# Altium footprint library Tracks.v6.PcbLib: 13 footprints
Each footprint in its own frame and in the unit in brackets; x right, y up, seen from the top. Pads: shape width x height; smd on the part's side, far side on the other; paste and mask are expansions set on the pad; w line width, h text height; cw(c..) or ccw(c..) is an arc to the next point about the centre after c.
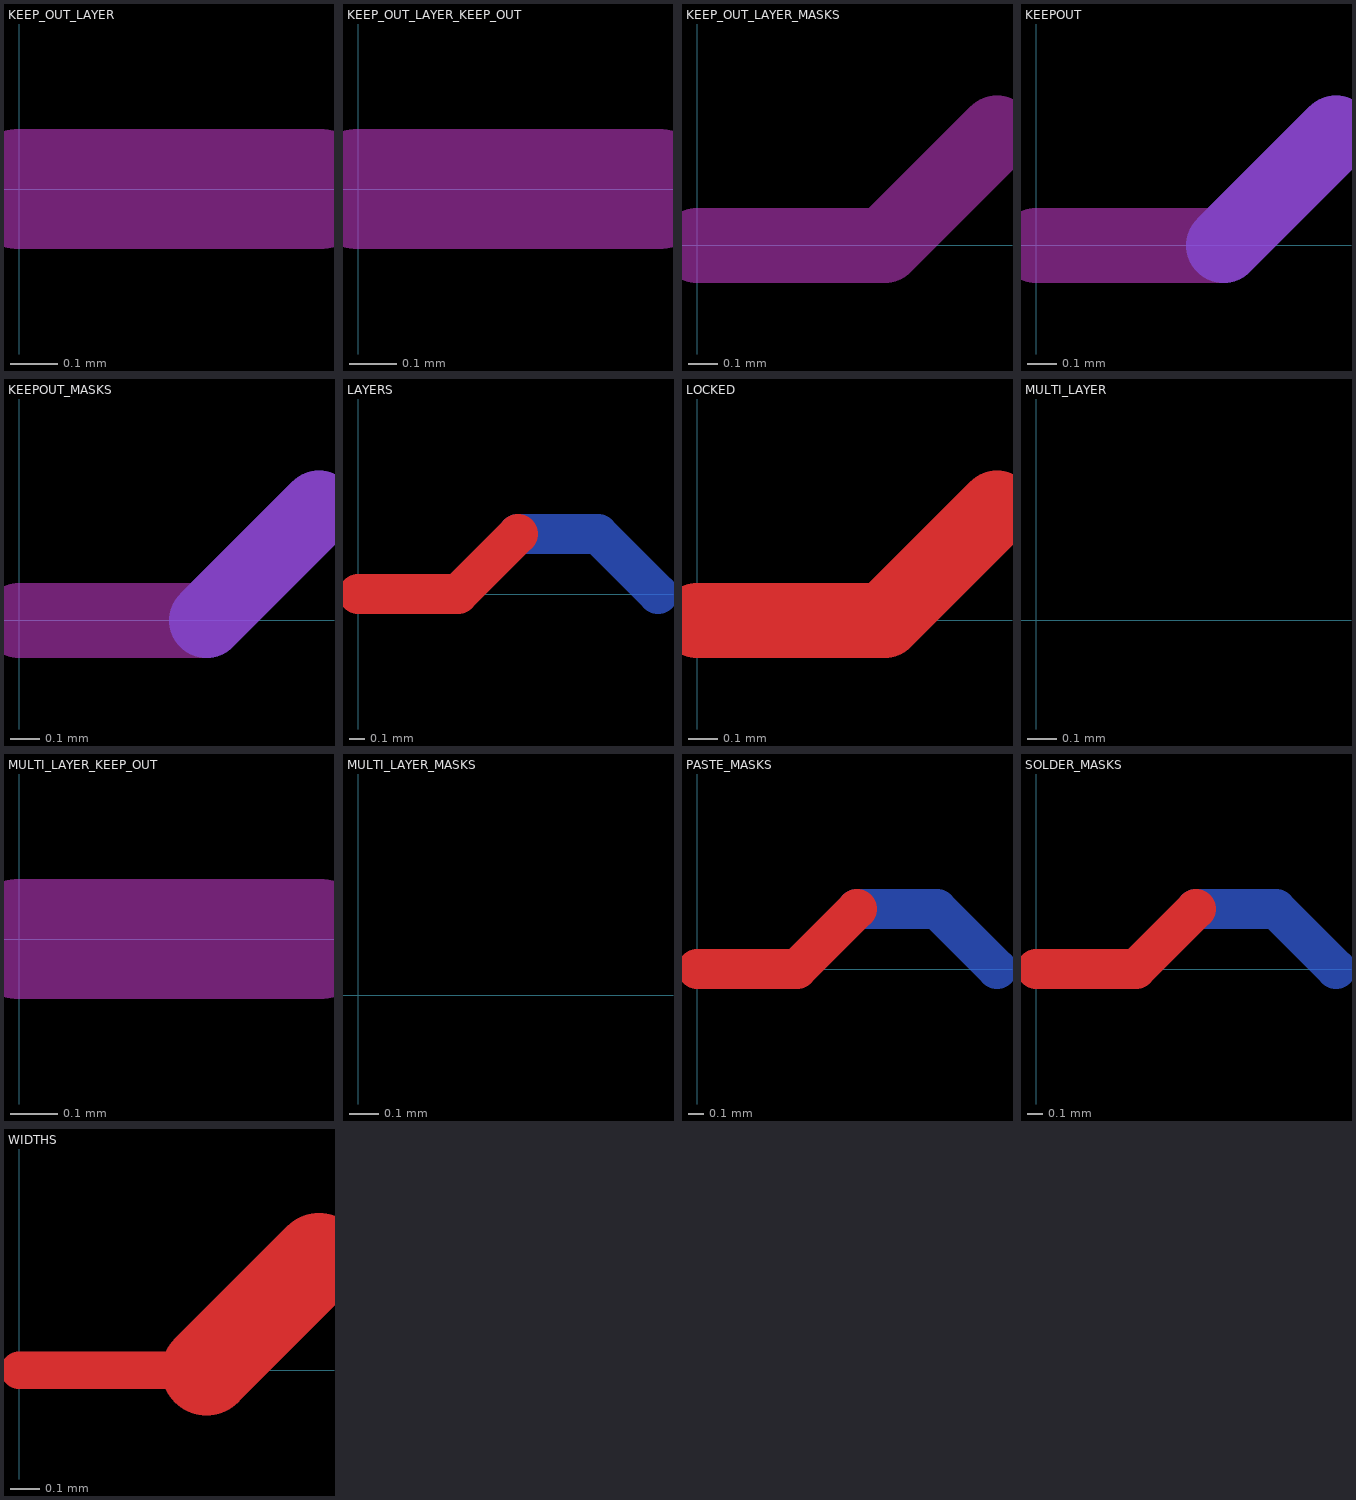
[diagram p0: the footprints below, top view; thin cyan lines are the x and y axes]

## KEEP_OUT_LAYER [mm]
Keep-Out Layer:
  lines w0.254: 0,0 0.635,0

## KEEP_OUT_LAYER_KEEP_OUT [mm]
Keep-Out Layer:
  lines w0.254: 0,0 0.635,0

## KEEP_OUT_LAYER_MASKS [mm]
Keep-Out Layer:
  lines w0.254: 0,0 0.635,0 1.016,0.381

## KEEPOUT [mm]
Top Layer keep-out:
  lines w0.254: 0,0 0.635,0
Bottom Layer keep-out:
  lines w0.254: 0.635,0 1.016,0.381

## KEEPOUT_MASKS [mm]
Top Layer keep-out:
  lines w0.254: 0,0 0.635,0
Bottom Layer keep-out:
  lines w0.254: 0.635,0 1.016,0.381

## LAYERS [mm]
Top Layer:
  lines w0.254: 0,0 0.635,0 1.016,0.381
Bottom Layer:
  lines w0.254: 1.016,0.381 1.524,0.381 1.905,0

## LOCKED [mm]
Top Layer:
  lines w0.254: 0,0 0.635,0 1.016,0.381

## MULTI_LAYER [mm]
Multi-Layer:
  lines w0.254: 0,0 0.635,0 1.016,0.381

## MULTI_LAYER_KEEP_OUT [mm]
Multi-Layer keep-out:
  lines w0.254: 0,0 0.635,0

## MULTI_LAYER_MASKS [mm]
Multi-Layer:
  lines w0.254: 0,0 0.635,0 1.016,0.381

## PASTE_MASKS [mm]
Top Layer:
  lines w0.254: 0,0 0.635,0 1.016,0.381
Bottom Layer:
  lines w0.254: 1.016,0.381 1.524,0.381 1.905,0

## SOLDER_MASKS [mm]
Top Layer:
  lines w0.254: 0,0 0.635,0 1.016,0.381
Bottom Layer:
  lines w0.254: 1.016,0.381 1.524,0.381 1.905,0

## WIDTHS [mm]
Top Layer:
  lines w0.127: 0,0 0.635,0
  lines w0.305: 0.635,0 1.016,0.381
